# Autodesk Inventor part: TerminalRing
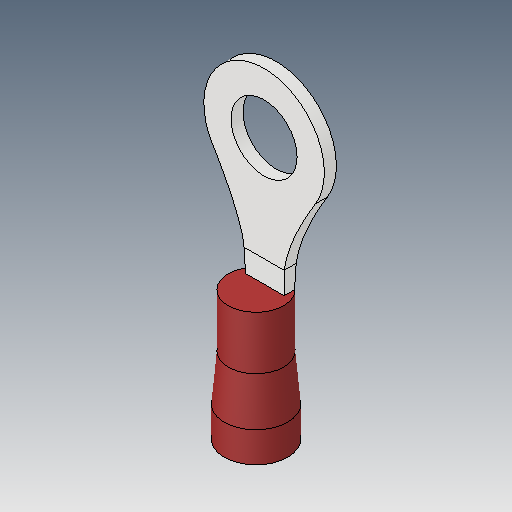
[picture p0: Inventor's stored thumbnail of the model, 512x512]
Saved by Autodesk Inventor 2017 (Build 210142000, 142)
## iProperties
Created: 2005-03
Part Number: TerminalRing
Material: Generic
Document SubType Name: Modeling
Designer: DanielSeverino
Categories: <MemberInstance><Categories><Category DisplayName="" Mnemonic="CABLEANDHARNESS" InternalName="e4a7e005-5e42-4d16-b293-125e7f0d0512"><Category DisplayName="" Mne
Density: 1 g/cm^3
Appearance: Default
GlobalPropertyList: <PropertyList/>
Author: Prof. Daniel Severino
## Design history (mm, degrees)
feature "Solid1"
sketch "Sketch1"
  geometry: C1 r 2.082 at (0, 0) reference
node "1"
body "Solid2"
